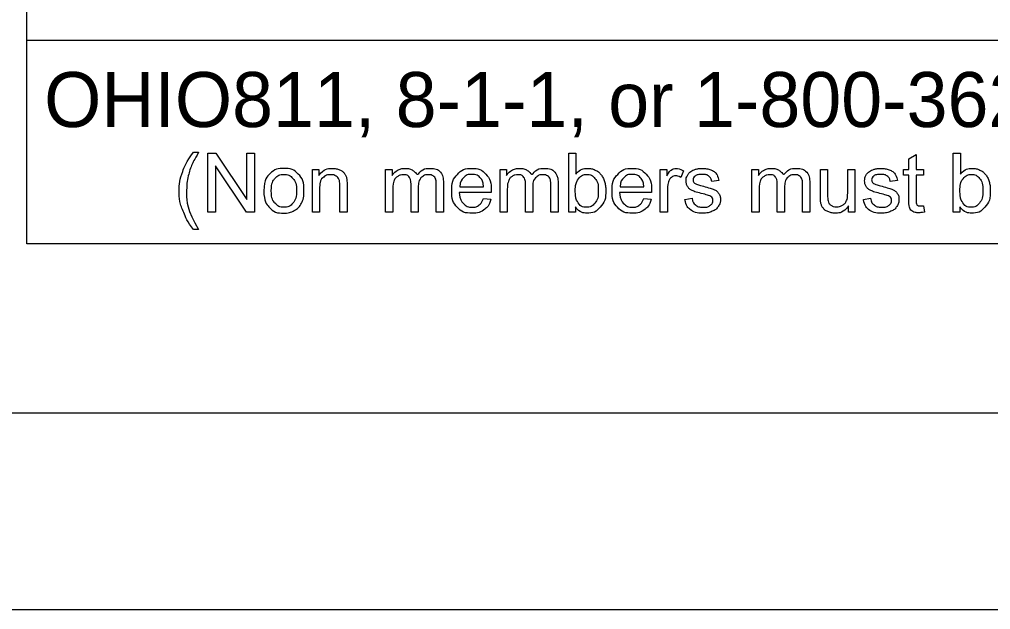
# Model space of a CAD drawing. Extents: x 0 to 70.2, y 0 to 31.4.
# Drawn here: x 2.37 to 4.842, y 0 to 1.503 of the extents above; entities that cross this region are included whole.
import ezdxf

# ---------------------------------------------------------------- set-up
doc = ezdxf.new("R2010")
doc.units = 0
for name, color, linetype in [('SH_Border', 7, 'Continuous'), ('SH_Cut_Line', 7, 'Continuous'), ('SH_Data', 7, 'Continuous'), ('SH_Text', 7, 'Continuous')]:
    doc.layers.add(name, color=color, linetype=linetype)

msp = doc.modelspace()

# ---------------------------------------------------------------- linework, layer by layer
at = {"layer": 'SH_Border'}
msp.add_lwpolyline([(1.5, 21.5), (33.5, 21.5), (33.5, 0.5), (1.5, 0.5)], close=True, dxfattribs=at)
at = {"layer": 'SH_Cut_Line'}
msp.add_lwpolyline([(0, 0), (34, 0), (34, 22), (0, 22)], close=True, dxfattribs=at)
at = {"layer": 'SH_Data'}
for p, q in [((2.3882, 0.9308), (2.3882, 3.2683)), ((6.6382, 1.4486), (2.3882, 1.4486)), ((6.6382, 0.9308), (2.3882, 0.9308))]:
    msp.add_line(p, q, dxfattribs=at)
at = {"layer": 'SH_Text'}
for points in [[(2.8128, 1.1646), (2.826, 1.1646)], [(2.8496, 1.0119), (2.8496, 1.1621), (2.8699, 1.1621), (2.9489, 1.0441), (2.9489, 1.1621), (2.9679, 1.1621), (2.9679, 1.0119), (2.9476, 1.0119), (2.8686, 1.1298), (2.8686, 1.0119), (2.8496, 1.0119)], [(3.785, 1.0119), (3.768, 1.0119), (3.768, 1.1621), (3.7864, 1.1621), (3.7864, 1.1085)], [(4.7641, 1.0119), (4.747, 1.0119), (4.747, 1.1621), (4.7655, 1.1621), (4.7655, 1.1085)], [(4.634, 1.0438), (4.634, 1.1064), (4.6203, 1.1064), (4.6203, 1.1207), (4.634, 1.1207), (4.634, 1.1477), (4.6524, 1.1587), (4.6524, 1.1207), (4.6708, 1.1207), (4.6708, 1.1064), (4.6524, 1.1064), (4.6524, 1.0427)], [(3.1155, 1.0119), (3.1155, 1.1207), (3.1321, 1.1207), (3.1321, 1.1053)], [(3.3019, 1.0119), (3.3019, 1.1207), (3.3184, 1.1207), (3.3184, 1.1054)], [(3.5933, 1.0119), (3.5933, 1.1207), (3.6098, 1.1207), (3.6098, 1.1054)], [(4.0011, 1.0119), (4.0011, 1.1207), (4.0177, 1.1207), (4.0177, 1.1042)], [(4.0601, 1.1173), (4.0537, 1.1002)], [(4.2343, 1.0119), (4.2343, 1.1207), (4.2508, 1.1207), (4.2508, 1.1054)], [(4.4086, 1.0533), (4.4086, 1.1207), (4.4271, 1.1207), (4.4271, 1.0604)], [(4.4783, 1.0625), (4.4783, 1.1207), (4.4967, 1.1207), (4.4967, 1.0119), (4.4803, 1.0119)], [(4.1501, 1.0926), (4.132, 1.0902)], [(4.6047, 1.0926), (4.5866, 1.0902)], [(3.134, 1.0713), (3.134, 1.0119), (3.1155, 1.0119)], [(3.2039, 1.0788), (3.2039, 1.0119), (3.1855, 1.0119), (3.1855, 1.078)], [(3.3204, 1.0683), (3.3204, 1.0119), (3.3019, 1.0119)], [(3.385, 1.0751), (3.385, 1.0119), (3.3666, 1.0119), (3.3666, 1.0825)], [(3.4495, 1.0866), (3.4495, 1.0119), (3.431, 1.0119), (3.431, 1.0804)], [(3.4906, 1.0767), (3.5513, 1.0767)], [(3.6117, 1.0683), (3.6117, 1.0119), (3.5933, 1.0119)], [(3.6764, 1.0751), (3.6764, 1.0119), (3.658, 1.0119), (3.658, 1.0825)], [(3.7408, 1.0866), (3.7408, 1.0119), (3.7224, 1.0119), (3.7224, 1.0804)], [(3.8986, 1.0767), (3.9593, 1.0767)], [(4.0195, 1.0689), (4.0195, 1.0119), (4.0011, 1.0119)], [(4.2527, 1.0683), (4.2527, 1.0119), (4.2343, 1.0119)], [(4.3174, 1.0751), (4.3174, 1.0119), (4.299, 1.0119), (4.299, 1.0825)], [(4.3818, 1.0866), (4.3818, 1.0119), (4.3634, 1.0119), (4.3634, 1.0804)], [(3.5707, 1.0616), (3.4895, 1.0616)], [(3.5511, 1.047), (3.5702, 1.0446)], [(3.9787, 1.0616), (3.8975, 1.0616)], [(3.9591, 1.047), (3.9782, 1.0446)], [(4.0637, 1.0444), (4.0819, 1.0473)], [(4.5183, 1.0444), (4.5365, 1.0473)], [(3.785, 1.0255), (3.785, 1.0119)], [(4.4803, 1.0119), (4.4803, 1.028)], [(4.6708, 1.0283), (4.6734, 1.0121)], [(4.7641, 1.0255), (4.7641, 1.0119)], [(2.826, 0.9677), (2.8128, 0.9677)]]:
    msp.add_lwpolyline(points, dxfattribs=at)
for points in [[(2.8128, 0.9677), (2.7975, 0.987), (2.787, 1.0128), (2.7764, 1.0386), (2.7764, 1.0663), (2.7764, 1.0906), (2.7843, 1.113), (2.7936, 1.1389), (2.8128, 1.1646)], [(2.826, 1.1646), (2.8136, 1.1433), (2.8096, 1.1342), (2.8034, 1.12), (2.7998, 1.1047), (2.7954, 1.0855), (2.7954, 1.0662), (2.7954, 1.0169), (2.826, 0.9677)], [(2.992, 1.0663), (2.992, 1.0965), (3.0088, 1.1111), (3.0229, 1.1231), (3.043, 1.1231), (3.0654, 1.1231), (3.0797, 1.1085), (3.0939, 1.0938), (3.0939, 1.0679), (3.0939, 1.0469), (3.0876, 1.0348), (3.0813, 1.0228), (3.0693, 1.0162), (3.0573, 1.0095), (3.043, 1.0095), (3.0202, 1.0095), (3.0061, 1.0241), (2.992, 1.0388), (2.992, 1.0663)], [(3.1321, 1.1053), (3.1441, 1.1231), (3.1667, 1.1231), (3.1765, 1.1231), (3.1848, 1.1196), (3.193, 1.1161), (3.1971, 1.1103), (3.2012, 1.1046), (3.2029, 1.0967), (3.2039, 1.0916), (3.2039, 1.0788)], [(3.3184, 1.1054), (3.3235, 1.1134), (3.332, 1.1183), (3.3406, 1.1231), (3.3514, 1.1231), (3.3635, 1.1231), (3.3712, 1.1181), (3.379, 1.1131), (3.3822, 1.104), (3.3951, 1.1231), (3.4158, 1.1231), (3.432, 1.1231), (3.4407, 1.1142), (3.4495, 1.1052), (3.4495, 1.0866)], [(3.5702, 1.0446), (3.5657, 1.0279), (3.5535, 1.0187), (3.5413, 1.0095), (3.5223, 1.0095), (3.4985, 1.0095), (3.4845, 1.0242), (3.4705, 1.0389), (3.4705, 1.0654), (3.4705, 1.0928), (3.4847, 1.108), (3.4988, 1.1231), (3.5213, 1.1231), (3.5431, 1.1231), (3.557, 1.1083), (3.5708, 1.0934), (3.5708, 1.0665), (3.5708, 1.0649), (3.5707, 1.0616)], [(3.6098, 1.1054), (3.6149, 1.1134), (3.6234, 1.1183), (3.6319, 1.1231), (3.6428, 1.1231), (3.6549, 1.1231), (3.6626, 1.1181), (3.6704, 1.1131), (3.6735, 1.104), (3.6865, 1.1231), (3.7072, 1.1231), (3.7234, 1.1231), (3.7321, 1.1142), (3.7408, 1.1052), (3.7408, 1.0866)], [(3.7864, 1.1085), (3.7981, 1.1231), (3.8162, 1.1231), (3.8262, 1.1231), (3.8352, 1.1191), (3.8441, 1.1151), (3.8499, 1.1077), (3.8557, 1.1004), (3.859, 1.0901), (3.8623, 1.0797), (3.8623, 1.068), (3.8623, 1.04), (3.8484, 1.0248), (3.8346, 1.0095), (3.8152, 1.0095), (3.796, 1.0095), (3.785, 1.0255)], [(3.9782, 1.0446), (3.9737, 1.0279), (3.9615, 1.0187), (3.9493, 1.0095), (3.9303, 1.0095), (3.9065, 1.0095), (3.8925, 1.0242), (3.8785, 1.0389), (3.8785, 1.0654), (3.8785, 1.0928), (3.8927, 1.108), (3.9068, 1.1231), (3.9293, 1.1231), (3.9511, 1.1231), (3.965, 1.1083), (3.9788, 1.0934), (3.9788, 1.0665), (3.9788, 1.0649), (3.9787, 1.0616)], [(4.0177, 1.1042), (4.024, 1.1158), (4.0294, 1.1195), (4.0348, 1.1231), (4.0412, 1.1231), (4.0505, 1.1231), (4.0601, 1.1173)], [(4.0819, 1.0473), (4.0834, 1.0363), (4.0905, 1.0305), (4.0975, 1.0246), (4.1101, 1.0246), (4.1229, 1.0246), (4.1291, 1.0298), (4.1352, 1.035), (4.1352, 1.0419), (4.1352, 1.0482), (4.1298, 1.0518), (4.126, 1.0543), (4.1109, 1.0581), (4.0906, 1.0632), (4.0827, 1.0669), (4.0749, 1.0706), (4.0708, 1.0772), (4.0668, 1.0838), (4.0668, 1.0918), (4.0668, 1.0991), (4.0701, 1.1053), (4.0735, 1.1115), (4.0792, 1.1156), (4.0835, 1.1187), (4.0909, 1.1209), (4.0984, 1.1231), (4.1069, 1.1231), (4.1197, 1.1231), (4.1294, 1.1195), (4.1391, 1.1158), (4.1437, 1.1095), (4.1484, 1.1031), (4.1501, 1.0926)], [(4.2508, 1.1054), (4.2559, 1.1134), (4.2644, 1.1183), (4.2729, 1.1231), (4.2838, 1.1231), (4.2959, 1.1231), (4.3036, 1.1181), (4.3114, 1.1131), (4.3145, 1.104), (4.3275, 1.1231), (4.3482, 1.1231), (4.3644, 1.1231), (4.3731, 1.1142), (4.3818, 1.1052), (4.3818, 1.0866)], [(4.5365, 1.0473), (4.538, 1.0363), (4.545, 1.0305), (4.5521, 1.0246), (4.5647, 1.0246), (4.5775, 1.0246), (4.5836, 1.0298), (4.5898, 1.035), (4.5898, 1.0419), (4.5898, 1.0482), (4.5843, 1.0518), (4.5805, 1.0543), (4.5655, 1.0581), (4.5452, 1.0632), (4.5373, 1.0669), (4.5295, 1.0706), (4.5254, 1.0772), (4.5214, 1.0838), (4.5214, 1.0918), (4.5214, 1.0991), (4.5247, 1.1053), (4.528, 1.1115), (4.5338, 1.1156), (4.5381, 1.1187), (4.5455, 1.1209), (4.553, 1.1231), (4.5615, 1.1231), (4.5743, 1.1231), (4.584, 1.1195), (4.5937, 1.1158), (4.5983, 1.1095), (4.6029, 1.1031), (4.6047, 1.0926)], [(4.7655, 1.1085), (4.7771, 1.1231), (4.7953, 1.1231), (4.8053, 1.1231), (4.8143, 1.1191), (4.8232, 1.1151), (4.829, 1.1077), (4.8348, 1.1004), (4.8381, 1.0901), (4.8413, 1.0797), (4.8413, 1.068), (4.8413, 1.04), (4.8275, 1.0248), (4.8137, 1.0095), (4.7943, 1.0095), (4.7751, 1.0095), (4.7641, 1.0255)], [(3.011, 1.0663), (3.011, 1.0454), (3.0201, 1.035), (3.0292, 1.0246), (3.043, 1.0246), (3.0567, 1.0246), (3.0658, 1.0351), (3.0749, 1.0455), (3.0749, 1.0669), (3.0749, 1.0871), (3.0658, 1.0975), (3.0566, 1.1079), (3.043, 1.1079), (3.0292, 1.1079), (3.0201, 1.0976), (3.011, 1.0872), (3.011, 1.0663)], [(3.1855, 1.078), (3.1855, 1.0893), (3.1833, 1.0949), (3.1812, 1.1005), (3.1757, 1.1038), (3.1702, 1.1071), (3.1628, 1.1071), (3.1511, 1.1071), (3.1425, 1.0996), (3.134, 1.0922), (3.134, 1.0713)], [(3.3666, 1.0825), (3.3666, 1.0948), (3.3621, 1.101), (3.3576, 1.1071), (3.3473, 1.1071), (3.3395, 1.1071), (3.3329, 1.103), (3.3263, 1.0989), (3.3233, 1.091), (3.3204, 1.0832), (3.3204, 1.0683)], [(3.431, 1.0804), (3.431, 1.0915), (3.4292, 1.0963), (3.4274, 1.1012), (3.4227, 1.1042), (3.418, 1.1071), (3.4117, 1.1071), (3.4002, 1.1071), (3.3926, 1.0995), (3.385, 1.0919), (3.385, 1.0751)], [(3.5513, 1.0767), (3.5501, 1.0905), (3.5444, 1.0973), (3.5355, 1.108), (3.5215, 1.108), (3.5088, 1.108), (3.5001, 1.0995), (3.4915, 1.091), (3.4906, 1.0767)], [(3.658, 1.0825), (3.658, 1.0948), (3.6535, 1.101), (3.6489, 1.1071), (3.6387, 1.1071), (3.6309, 1.1071), (3.6243, 1.103), (3.6177, 1.0989), (3.6147, 1.091), (3.6117, 1.0832), (3.6117, 1.0683)], [(3.7224, 1.0804), (3.7224, 1.0915), (3.7206, 1.0963), (3.7188, 1.1012), (3.7141, 1.1042), (3.7094, 1.1071), (3.703, 1.1071), (3.6916, 1.1071), (3.684, 1.0995), (3.6764, 1.0919), (3.6764, 1.0751)], [(3.7848, 1.0671), (3.7848, 1.0476), (3.7901, 1.0389), (3.7988, 1.0246), (3.8136, 1.0246), (3.8257, 1.0246), (3.8345, 1.0351), (3.8433, 1.0456), (3.8433, 1.0664), (3.8433, 1.0877), (3.8348, 1.0979), (3.8264, 1.108), (3.8144, 1.108), (3.8024, 1.108), (3.7936, 1.0975), (3.7848, 1.087), (3.7848, 1.0671)], [(3.9593, 1.0767), (3.9581, 1.0905), (3.9524, 1.0973), (3.9435, 1.108), (3.9295, 1.108), (3.9168, 1.108), (3.9081, 1.0995), (3.8995, 1.091), (3.8986, 1.0767)], [(4.0537, 1.1002), (4.047, 1.1041), (4.0402, 1.1041), (4.0342, 1.1041), (4.0294, 1.1005), (4.0246, 1.0969), (4.0226, 1.0904), (4.0195, 1.0806), (4.0195, 1.0689)], [(4.132, 1.0902), (4.1308, 1.0986), (4.1249, 1.1033), (4.119, 1.108), (4.1082, 1.108), (4.0955, 1.108), (4.0901, 1.1038), (4.0846, 1.0996), (4.0846, 1.094), (4.0846, 1.0904), (4.0869, 1.0875), (4.0891, 1.0845), (4.094, 1.0826), (4.0967, 1.0816), (4.1103, 1.0779), (4.1299, 1.0727), (4.1376, 1.0693), (4.1454, 1.066), (4.1498, 1.0597), (4.1542, 1.0533), (4.1542, 1.0439), (4.1542, 1.0347), (4.1488, 1.0265), (4.1434, 1.0184), (4.1333, 1.014), (4.1231, 1.0095), (4.1103, 1.0095), (4.089, 1.0095), (4.0779, 1.0183), (4.0668, 1.0271), (4.0637, 1.0444)], [(4.299, 1.0825), (4.299, 1.0948), (4.2945, 1.101), (4.2899, 1.1071), (4.2797, 1.1071), (4.2719, 1.1071), (4.2653, 1.103), (4.2587, 1.0989), (4.2557, 1.091), (4.2527, 1.0832), (4.2527, 1.0683)], [(4.3634, 1.0804), (4.3634, 1.0915), (4.3616, 1.0963), (4.3598, 1.1012), (4.3551, 1.1042), (4.3504, 1.1071), (4.344, 1.1071), (4.3326, 1.1071), (4.325, 1.0995), (4.3174, 1.0919), (4.3174, 1.0751)], [(4.5866, 1.0902), (4.5854, 1.0986), (4.5795, 1.1033), (4.5736, 1.108), (4.5628, 1.108), (4.5501, 1.108), (4.5446, 1.1038), (4.5392, 1.0996), (4.5392, 1.094), (4.5392, 1.0904), (4.5415, 1.0875), (4.5437, 1.0845), (4.5485, 1.0826), (4.5513, 1.0816), (4.5648, 1.0779), (4.5844, 1.0727), (4.5922, 1.0693), (4.5999, 1.066), (4.6044, 1.0597), (4.6088, 1.0533), (4.6088, 1.0439), (4.6088, 1.0347), (4.6034, 1.0265), (4.598, 1.0184), (4.5878, 1.014), (4.5777, 1.0095), (4.5649, 1.0095), (4.5436, 1.0095), (4.5325, 1.0183), (4.5213, 1.0271), (4.5183, 1.0444)], [(4.7639, 1.0671), (4.7639, 1.0476), (4.7692, 1.0389), (4.7779, 1.0246), (4.7927, 1.0246), (4.8048, 1.0246), (4.8135, 1.0351), (4.8223, 1.0456), (4.8223, 1.0664), (4.8223, 1.0877), (4.8139, 1.0979), (4.8055, 1.108), (4.7935, 1.108), (4.7814, 1.108), (4.7727, 1.0975), (4.7639, 1.087), (4.7639, 1.0671)], [(3.4895, 1.0616), (3.4906, 1.0437), (3.4997, 1.0341), (3.5088, 1.0246), (3.5224, 1.0246), (3.5326, 1.0246), (3.5397, 1.03), (3.5469, 1.0353), (3.5511, 1.047)], [(3.8975, 1.0616), (3.8985, 1.0437), (3.9077, 1.0341), (3.9168, 1.0246), (3.9304, 1.0246), (3.9406, 1.0246), (3.9477, 1.03), (3.9549, 1.0353), (3.9591, 1.047)], [(4.4803, 1.028), (4.4676, 1.0095), (4.4458, 1.0095), (4.4362, 1.0095), (4.4278, 1.0132), (4.4195, 1.0169), (4.4154, 1.0225), (4.4114, 1.028), (4.4098, 1.0361), (4.4086, 1.0416), (4.4086, 1.0533)], [(4.4271, 1.0604), (4.4271, 1.046), (4.4282, 1.041), (4.4299, 1.0337), (4.4355, 1.0296), (4.4412, 1.0254), (4.4495, 1.0254), (4.4578, 1.0254), (4.465, 1.0297), (4.4723, 1.0339), (4.4753, 1.0412), (4.4783, 1.0486), (4.4783, 1.0625)], [(4.6734, 1.0121), (4.6657, 1.0104), (4.6595, 1.0104), (4.6495, 1.0104), (4.644, 1.0136), (4.6385, 1.0168), (4.6362, 1.022), (4.634, 1.0271), (4.634, 1.0438)], [(4.6524, 1.0427), (4.6524, 1.0348), (4.6534, 1.0325), (4.6543, 1.0303), (4.6565, 1.0289), (4.6587, 1.0276), (4.6628, 1.0276), (4.6658, 1.0276), (4.6708, 1.0283)]]:
    msp.add_open_spline(points, degree=3, dxfattribs=at)

# ---------------------------------------------------------------- texts
msp.add_text('OHIO811, 8-1-1, or 1-800-362-2764', height=0.14, dxfattribs=at).set_placement((2.4327, 1.2286))

doc.saveas('drawing.dxf')
